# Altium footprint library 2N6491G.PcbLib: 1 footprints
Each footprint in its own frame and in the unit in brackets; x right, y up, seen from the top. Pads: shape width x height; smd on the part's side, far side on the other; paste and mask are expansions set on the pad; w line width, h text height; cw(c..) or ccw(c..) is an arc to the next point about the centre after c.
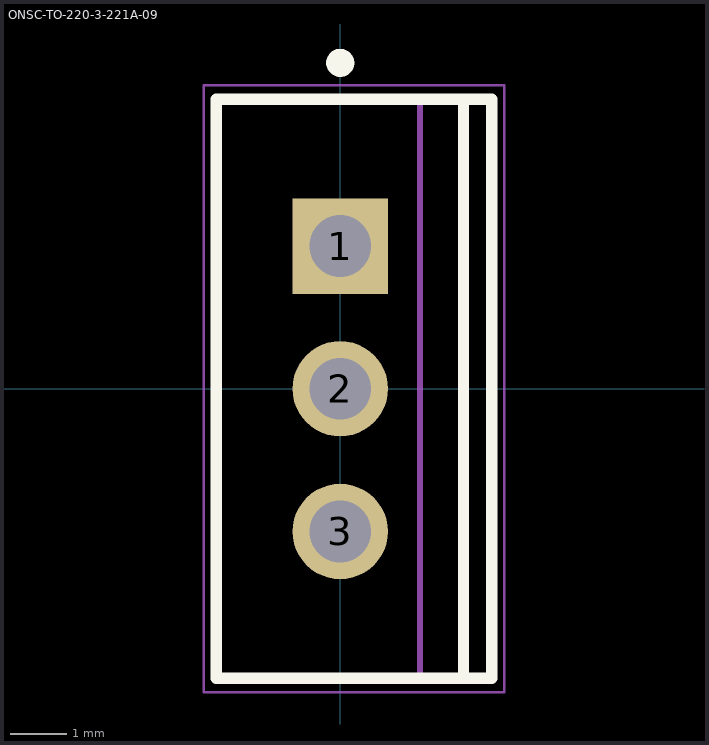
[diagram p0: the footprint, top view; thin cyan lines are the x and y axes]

## ONSC-TO-220-3-221A-09 [mm] "FM, 3-Leads, Body 10.3x4.85mm, Pitch 2.54mm"
height 19.85
pads (3):
  rect 1.7x1.7 hole 1.1: 1(0,2.54)
  round 1.7 hole 1.1: 2(0,0) 3(0,-2.54)
Top Overlay:
  circle w0.25: c0,5.8 r0.125
  lines w0.2: 2.195,-5.15 2.195,5.15 ; -2.205,-5.15 2.695,-5.15 2.695,5.15 -2.205,5.15 -2.205,-5.15
Mechanical 13:
  lines w0.1: 1.42,-5.15 1.42,5.15 ; -2.18,-5.15 -2.18,5.15 2.67,5.15 2.67,-5.15 -2.18,-5.15
Mechanical 15:
  lines w0.05: -2.43,-5.4 -2.43,5.4 2.92,5.4 2.92,-5.4 -2.43,-5.4
  lines w0.1: -0.5,0 0.5,0 ; 0,-0.5 0,0.5
3D body: height 2.8, standoff 0, extent -0.25,1.87 0.25,3.21
3D body: height 0, standoff -1.6, extent -0.25,2.15 0.25,2.93
3D body: height 2.8, standoff 0, extent -0.25,-0.67 0.25,0.67
3D body: height 0, standoff -1.6, extent -0.25,-0.39 0.25,0.39
3D body: height 2.8, standoff 0, extent -0.25,-3.21 0.25,-1.87
3D body: height 0, standoff -1.6, extent -0.25,-2.93 0.25,-2.15
3D body: height 13.65, standoff 2.8, extent -2.18,-5.15 2.67,5.15
3D body: height 15.13, standoff 13.65, extent 1.42,-4.975 2.67,4.975
3D body: height 15.17, standoff 15.13, extent 1.42,0.376 2.67,4.975
3D body: height 15.17, standoff 15.13, extent 1.42,-4.975 2.67,-0.376
3D body: height 18.98, standoff 18.94, extent 1.42,0.376 2.67,4.975
3D body: height 18.98, standoff 18.94, extent 1.42,-4.975 2.67,-0.376
3D body: height 15.28, standoff 15.16, extent 1.42,0.737 2.67,4.975
3D body: height 15.28, standoff 15.16, extent 1.42,-4.975 2.67,-0.737
3D body: height 18.94, standoff 18.83, extent 1.42,0.737 2.67,4.975
3D body: height 18.94, standoff 18.83, extent 1.42,-4.975 2.67,-0.737
3D body: height 15.45, standoff 15.27, extent 1.42,1.069 2.67,4.975
3D body: height 15.45, standoff 15.27, extent 1.42,-4.975 2.67,-1.069
3D body: height 18.83, standoff 18.65, extent 1.42,1.069 2.67,4.975
3D body: height 18.83, standoff 18.65, extent 1.42,-4.975 2.67,-1.069
3D body: height 15.69, standoff 15.45, extent 1.42,1.361 2.67,4.975
3D body: height 15.69, standoff 15.45, extent 1.42,-4.975 2.67,-1.361
3D body: height 18.66, standoff 18.41, extent 1.42,1.361 2.67,4.975
3D body: height 18.66, standoff 18.41, extent 1.42,-4.975 2.67,-1.361
3D body: height 15.99, standoff 15.69, extent 1.42,1.601 2.67,4.975
3D body: height 15.99, standoff 15.69, extent 1.42,-4.975 2.67,-1.601
3D body: height 18.42, standoff 18.12, extent 1.42,1.601 2.67,4.975
3D body: height 18.42, standoff 18.12, extent 1.42,-4.975 2.67,-1.601
3D body: height 16.32, standoff 15.98, extent 1.42,1.778 2.67,4.975
3D body: height 16.32, standoff 15.98, extent 1.42,-4.975 2.67,-1.778
3D body: height 18.12, standoff 17.79, extent 1.42,1.778 2.67,4.975
3D body: height 18.12, standoff 17.79, extent 1.42,-4.975 2.67,-1.778
3D body: height 16.68, standoff 16.31, extent 1.42,1.888 2.67,4.975
3D body: height 16.68, standoff 16.31, extent 1.42,-4.975 2.67,-1.888
3D body: height 17.79, standoff 17.43, extent 1.42,1.888 2.67,4.975
3D body: height 17.79, standoff 17.43, extent 1.42,-4.975 2.67,-1.888
3D body: height 17.05, standoff 16.67, extent 1.42,1.925 2.67,4.975
3D body: height 17.05, standoff 16.67, extent 1.42,-4.975 2.67,-1.925
3D body: height 17.43, standoff 17.05, extent 1.42,1.925 2.67,4.975
3D body: height 17.43, standoff 17.05, extent 1.42,-4.975 2.67,-1.925
3D body: height 19.85, standoff 18.98, extent 1.42,-4.975 2.67,4.975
